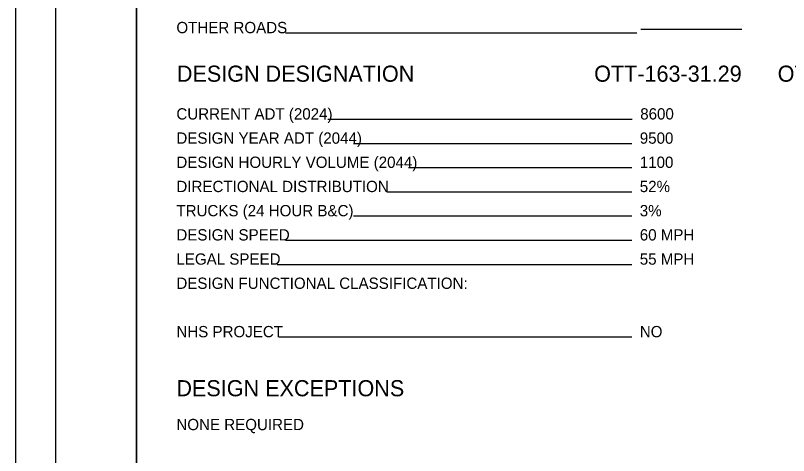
# Model space of a CAD drawing. Extents: x 0 to 34, y 0 to 22.
# Drawn here: x 0 to 9.58, y 5.64 to 11.1 of the extents above; entities that cross this region are included whole.
import ezdxf

# ---------------------------------------------------------------- set-up
doc = ezdxf.new("R2010")
doc.units = 0
for name, color, linetype in [('SH_Border', 7, 'Continuous'), ('SH_Cut_Line', 7, 'Continuous'), ('SH_Data', 7, 'Continuous'), ('SH_Text', 7, 'Continuous')]:
    doc.layers.add(name, color=color, linetype=linetype)

msp = doc.modelspace()

# ---------------------------------------------------------------- linework, layer by layer
at = {"layer": 'SH_Border'}
for points in [[(0.5, 21.5), (1.5, 21.5), (1.5, 0.5), (0.5, 0.5)], [(1.5, 21.5), (33.5, 21.5), (33.5, 0.5), (1.5, 0.5)]]:
    msp.add_lwpolyline(points, close=True, dxfattribs=at)
at = {"layer": 'SH_Cut_Line'}
msp.add_lwpolyline([(0, 0), (34, 0), (34, 22), (0, 22)], close=True, dxfattribs=at)
at = {"layer": 'SH_Data'}
for p, q in [((9, 10.9223), (7.75, 10.9223)), ((7.7, 10.8767), (3.3471, 10.8767)), ((7.6424, 9.8062), (3.871, 9.8062)), ((7.6368, 9.5062), (4.1885, 9.5062)), ((7.6368, 9.2062), (4.8723, 9.2062)), ((7.6368, 8.9062), (4.6037, 8.9062)), ((7.6368, 8.6062), (4.1885, 8.6062)), ((7.6368, 8.3062), (3.346, 8.3062)), ((7.6368, 8.0062), (3.2422, 8.0062)), ((7.6368, 7.1062), (3.2669, 7.1062))]:
    msp.add_line(p, q, dxfattribs=at)

# ---------------------------------------------------------------- texts
msp.add_text('DESIGN DESIGNATION                              OTT-163-31.29      OTT-163-31.70', height=0.2, dxfattribs=at).set_placement((2, 10.2747))
at = {"layer": 'SH_Text'}
for s, height, p in [('OTHER ROADS', 0.14, (1.9944, 10.8767)), ('CURRENT ADT (2024)', 0.14, (1.9944, 9.8062)), ('8600                                   11500', 0.14, (7.7424, 9.8062)), ('DESIGN YEAR ADT (2044)', 0.14, (1.9944, 9.5062)), ('9500                                   12000', 0.14, (7.7368, 9.5062)), ('DESIGN HOURLY VOLUME (2044)', 0.14, (1.9944, 9.2062)), ('1100                                   1400', 0.14, (7.7368, 9.2062)), ('DIRECTIONAL DISTRIBUTION', 0.14, (1.9944, 8.9062)), ('52%                                     53%', 0.14, (7.7368, 8.9062)), ('TRUCKS (24 HOUR B&C)', 0.14, (1.9944, 8.6062)), ('3%                                        4%', 0.14, (7.7368, 8.6062)), ('DESIGN SPEED', 0.14, (1.9944, 8.3062)), ('60 MPH                           60 MPH', 0.14, (7.7368, 8.3062)), ('LEGAL SPEED', 0.14, (1.9944, 8.0062)), ('55 MPH                           55 MPH', 0.14, (7.7368, 8.0062)), ('DESIGN FUNCTIONAL CLASSIFICATION:', 0.14, (1.9944, 7.7062)), ('NHS PROJECT', 0.14, (1.9944, 7.1062)), ('NO', 0.14, (7.7368, 7.1062)), ('DESIGN EXCEPTIONS', 0.2, (1.9944, 6.3744)), ('NONE REQUIRED', 0.14, (1.9944, 5.9544))]:
    msp.add_text(s, height=height, dxfattribs=at).set_placement(p)

doc.saveas('drawing.dxf')
